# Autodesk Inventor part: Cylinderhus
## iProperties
Created: 2001-12
Part Number: Cylinderhus
Material: SS2172
Document SubType Name: Modeling
Designer: Tobben
Control State: 0
Master: False
Checked Out: False
Shininess: 29.0
Length Units: 11269
Angle Units: 11279
Time Units: 11290
Mass Units: 11283
Length Display Precision: 3
Angle Display Precision: 2
Density: 0.0
Volumn: 0.0
Area: 0.0
PropertySet Name: Model Information
Author: Tobben
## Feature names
1. Extrusion1
2. Extrusion2
3. Extrusion3
4. Extrusion4
5. Extrusion5
6. Extrusion6
7. Hole1
8. Extrusion7
